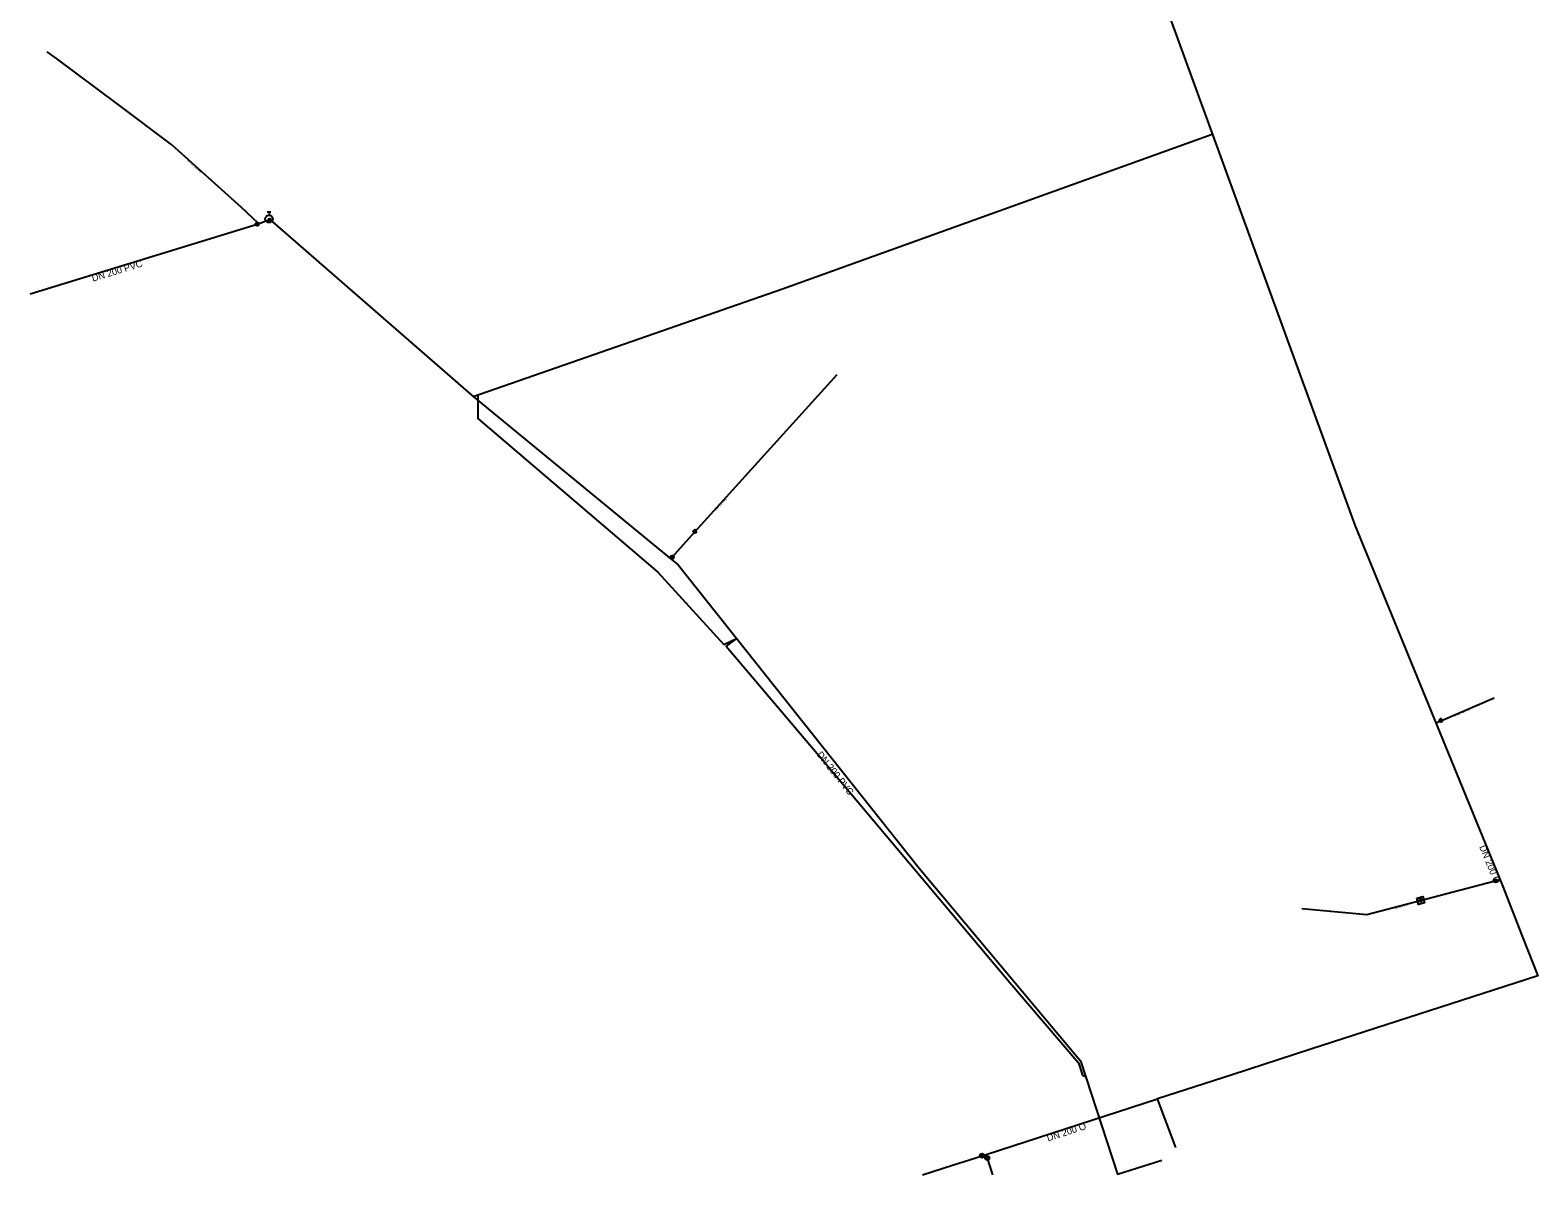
# Model space of a CAD drawing. Extents: x -491015 to -489994, y -1125687 to -1125176.
# Drawn here: x -491015 to -490661.8, y -1125687.5 to -1125419.4 of the extents above; entities that cross this region are included whole.
import ezdxf

# ---------------------------------------------------------------- set-up
doc = ezdxf.new("R2010")
doc.units = 0
for name, color, linetype in [('_hydrantova_odbocka_', 7, 'Continuous'), ('_pripojka_prevzato_z_dokumentace_', 7, 'Continuous'), ('_sachta_voda_', 7, 'Continuous'), ('_voda_projekt_smvak_', 7, 'Continuous'), ('_voda_smvak_prevzato_z_dokumentace_', 7, 'Continuous'), ('_voda_smvak_priblizne_', 7, 'Continuous'), ('Default', 7, 'Continuous'), ('MoLevel 2', 7, 'Continuous'), ('MoLevel 27', 7, 'Continuous'), ('MoLevel 28', 7, 'Continuous'), ('MoLevel 30', 7, 'Continuous'), ('MoLevel 46', 7, 'Continuous'), ('MoLevel 53', 7, 'Continuous'), ('MoLevel 55', 7, 'Continuous')]:
    doc.layers.add(name, color=color, linetype=linetype)

# ---------------------------------------------------------------- blocks, each defined once
blk = doc.blocks.new('_uzaver_')
at = {"layer": 'Default'}
for p, q in [((-0.035, -0.035), (0.035, 0.035)), ((0.035, -0.035), (-0.035, 0.035))]:
    blk.add_line(p, q, dxfattribs=at)
for radius in [0.05, 0.0025]:
    blk.add_circle((0, 0), radius, dxfattribs=at)
blk = doc.blocks.new('_uzaver_pripojka_')
at = {"layer": 'Default'}
for p, q in [((-0.035, -0.035), (0.035, 0.035)), ((0.035, -0.035), (-0.035, 0.035))]:
    blk.add_line(p, q, dxfattribs=at)
for radius in [0.05, 0.0025]:
    blk.add_circle((0, 0), radius, dxfattribs=at)
blk = doc.blocks.new('_hydrant_voda_')
at = {"layer": 'Default'}
for p, q in [((-0.0225, 0.095), (0.0225, 0.095)), ((0, 0.095), (0, 0.05))]:
    blk.add_line(p, q, dxfattribs=at)
blk.add_circle((0, 0), 0.05, dxfattribs=at)
blk = doc.blocks.new('_sachta_voda_')
at = {"layer": 'Default'}
blk.add_lwpolyline([(-0.01, 0.065), (0, 0.035), (0.01, 0.065)], dxfattribs=at)
blk.add_circle((0, 0), 0.035, dxfattribs=at)

msp = doc.modelspace()

# ---------------------------------------------------------------- linework, layer by layer
at = {"layer": '_hydrantova_odbocka_'}
msp.add_line((-490958.89, -1125463.75), (-490959.05, -1125463.57), dxfattribs=at)
at = {"layer": '_pripojka_prevzato_z_dokumentace_'}
for p, q in [((-490859.32, -1125536.84), (-490825.97, -1125500)), ((-490684.59, -1125581.11), (-490672.1, -1125575.72)), ((-490685.75, -1125581.61), (-490684.59, -1125581.11))]:
    msp.add_line(p, q, dxfattribs=at)
for points in [[(-490961.81, -1125464.8), (-490961.61, -1125464.58), (-490965.53, -1125460.92), (-490981.79, -1125446.21), (-490994.39, -1125436.74), (-491008.8, -1125425.97), (-491011, -1125424.47)], [(-490864.96, -1125543.22), (-490864.59, -1125542.8), (-490859.32, -1125536.84)], [(-490717.11, -1125625.09), (-490701.92, -1125626.49), (-490670.7, -1125618.3)]]:
    msp.add_lwpolyline(points, dxfattribs=at)
at = {"layer": '_sachta_voda_'}
msp.add_lwpolyline([(-490690.2, -1125622.71), (-490688.75, -1125622.32), (-490688.37, -1125623.77), (-490689.82, -1125624.15)], close=True, dxfattribs=at)
at = {"layer": '_voda_projekt_smvak_'}
for points in [[(-490911.22, -1125505.2), (-490838.81, -1125479.96), (-490738.1, -1125443.72)], [(-490910.11, -1125504.84), (-490910.11, -1125510.34), (-490867.94, -1125546.33), (-490852.48, -1125563.23), (-490849.54, -1125561.84)], [(-490849.54, -1125561.84), (-490851.97, -1125563.69), (-490829.82, -1125589.79), (-490785.52, -1125642.4), (-490769.43, -1125661.28), (-490768.54, -1125664.12), (-490767.78, -1125664.45)]]:
    msp.add_lwpolyline(points, dxfattribs=at)
at = {"layer": '_voda_smvak_prevzato_z_dokumentace_'}
for p, q in [((-490791.08, -1125682.69), (-490750.92, -1125669.7)), ((-490746.64, -1125681.12), (-490750.92, -1125669.7)), ((-490792.03, -1125683), (-490791.08, -1125682.69)), ((-490791.08, -1125682.69), (-490790.81, -1125683.55)), ((-490790.81, -1125683.55), (-490789.61, -1125687.49))]:
    msp.add_line(p, q, dxfattribs=at)
for points in [[(-490748.71, -1125268.96), (-490748.72, -1125270.45), (-490749, -1125413.83), (-490704.7, -1125535.33), (-490670.2, -1125619.59), (-490665.49, -1125631.59), (-490661.85, -1125640.89), (-490714.98, -1125658.08), (-490733.48, -1125664.06), (-490750.92, -1125669.7)], [(-490805.97, -1125687.49), (-490798.97, -1125685.24), (-490792.03, -1125683), (-490792.03, -1125683)]]:
    msp.add_lwpolyline(points, dxfattribs=at)
at = {"layer": '_voda_smvak_priblizne_'}
msp.add_lwpolyline([(-491015, -1125481.13), (-490961.81, -1125464.8), (-490958.89, -1125463.75), (-490911.22, -1125505.2), (-490866.99, -1125541.58), (-490863.23, -1125544.62), (-490806.76, -1125615.66), (-490768.94, -1125660.75), (-490760.34, -1125687.36), (-490749.92, -1125684.02)], dxfattribs=at)

# ---------------------------------------------------------------- block references
at = {"layer": 'MoLevel 27', "xscale": 5, "yscale": 5}
msp.add_blockref('_uzaver_', (-490958.89, -1125463.75), dxfattribs=at)
at = {"layer": 'MoLevel 27', "yscale": 10}
for p, xscale, rotation in [((-490792.03, -1125683), 10, -162.07448639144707), ((-490790.81, -1125683.55), 10.000000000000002, -72.970830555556)]:
    msp.add_blockref('_uzaver_', p, dxfattribs=dict(at, xscale=xscale, rotation=rotation))
at = {"layer": 'MoLevel 28', "xscale": 17.636684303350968, "yscale": 17.636684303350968}
msp.add_blockref('_hydrant_voda_', (-490959.05, -1125463.57), dxfattribs=at)
at = {"layer": 'MoLevel 30', "xscale": 10, "yscale": 10}
for p in [(-490859.32, -1125536.84), (-490684.59, -1125581.11), (-490689.32, -1125623.19)]:
    msp.add_blockref('_sachta_voda_', p, dxfattribs=at)
at = {"layer": 'MoLevel 53', "xscale": 8, "yscale": 8}
for p in [(-490961.81, -1125464.8), (-490864.59, -1125542.8)]:
    msp.add_blockref('_uzaver_pripojka_', p, dxfattribs=at)
at = {"layer": 'MoLevel 53', "xscale": 8.000000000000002, "yscale": 7.999999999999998, "rotation": 14.710494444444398}
msp.add_blockref('_uzaver_pripojka_', (-490671.85, -1125618.6), dxfattribs=at)

# ---------------------------------------------------------------- texts
at = {"layer": 'MoLevel 2'}
for rotation, p in [(17.0642, (-491000.28, -1125478.29)), (308.4846, (-490830.85, -1125589.1))]:
    msp.add_text('DN 200 PVC', height=1.605, rotation=rotation, dxfattribs=at).set_placement(p)
at = {"layer": 'MoLevel 46'}
for rotation, p in [(292.2663, (-490675.6, -1125610.65)), (17.9211, (-490776.57, -1125679.68))]:
    msp.add_text('DN 200 O', height=1.605, rotation=rotation, dxfattribs=at).set_placement(p)
at = {"layer": 'MoLevel 55'}
for s, rotation, p in [('DN 40 - 6/4 PE', 317.8652, (-490978.27, -1125450.01)), ('DN 100 PVC', 47.8472, (-490854.2, -1125531.86)), ("DN 25 - 1'' PE", 23.3468, (-490681.46, -1125580.26)), ('DN 90 PVC', 14.7105, (-490695.51, -1125625.28))]:
    msp.add_text(s, height=0.455, rotation=rotation, dxfattribs=at).set_placement(p)

doc.saveas('drawing.dxf')
